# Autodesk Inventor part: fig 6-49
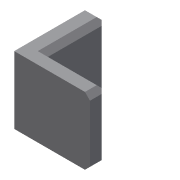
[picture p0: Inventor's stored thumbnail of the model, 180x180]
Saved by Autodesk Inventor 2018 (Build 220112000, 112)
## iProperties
Created: 2009-09
Part Number: fig 6-49
Document SubType Name: Modeling
Designer: Sham
Density: 1 g/cm^3
Material: Generic
Appearance: Default
Author: Sham
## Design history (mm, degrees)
sketch "Sketch1"
  geometry: L1 (1.789, 30)-(1.789, -5); L2 (1.789, -5)-(36.789, -5); L3 (36.789, -5)-(36.789, -15); L4 (36.789, -15)-(-8.211, -15); L5 (-8.211, -15)-(-8.211, 30); L6 (-8.211, 30)-(1.789, 30)
  constraints: 12 end point, 6 perpendicular
  dimensions: "d0" = 10 distance of L5.end L1.start; "d1" = 35 distance of L1.start L1.end; "d2" = 45 distance of L3.end L4.end; "d3" = 10 distance of L2.end L3.end (derived)
extrude "Extrusion1" new body sketch "Sketch1" distance "d4" = 40; taper "d5" = 0 deg
chamfer "Chamfer1" distance "d6" = 3; stored, may be unused: second distance "d7" = 2, angle "d8" = 45 deg
body "Solid1"
other parameters: "d1" = 35
